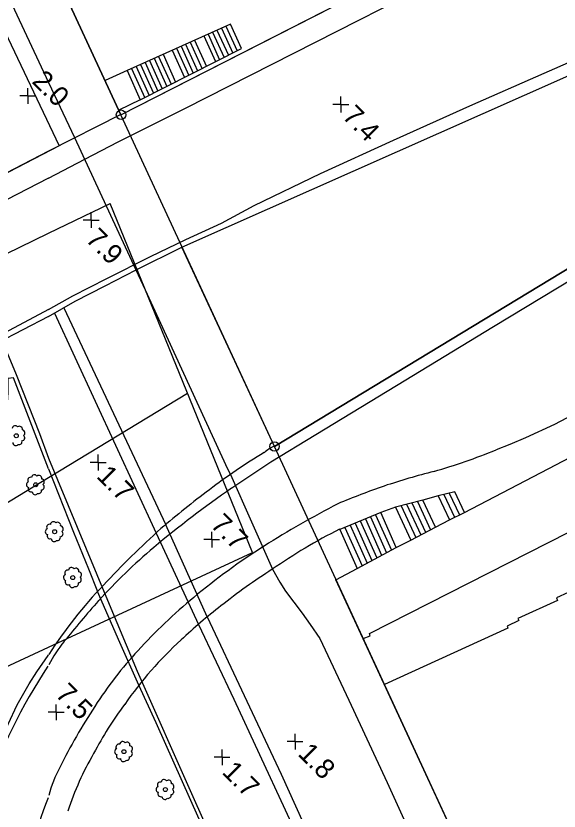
# Model space of a CAD drawing. Extents: x 1596643 to 1597288, y 13057194 to 13057957.
# Drawn here: x 1596964.2 to 1597032.9, y 13057515.8 to 13057616.2 of the extents above; entities that cross this region are included whole.
import ezdxf

# ---------------------------------------------------------------- set-up
doc = ezdxf.new("R2010")
doc.units = 0
for name, color, linetype in [('BAS bro ej def L', 7, 'Continuous'), ('BAS byggnad anläggning L', 7, 'Continuous'), ('BAS fastighetsgräns samfällighet L', 7, 'Continuous'), ('BAS gränspunkt P', 7, 'Continuous'), ('BAS Level 16', 7, 'Continuous'), ('BAS Level 19', 7, 'Continuous'), ('BAS Level 37', 7, 'Continuous'), ('BAS lövträd P', 7, 'Continuous'), ('BAS markytetext T', 7, 'Continuous'), ('BAS trappa L', 7, 'Continuous'), ('BAS vägbanekant L', 7, 'Continuous'), ('BAS vägbanekant skymd L', 7, 'Continuous')]:
    doc.layers.add(name, color=color, linetype=linetype)

msp = doc.modelspace()

# ---------------------------------------------------------------- linework, layer by layer
at = {"layer": 'BAS bro ej def L'}
for points in [[(1596977.5, 13057603.75), (1596968.37, 13057599.11)], [(1596968.37, 13057599.11), (1596945.61, 13057587.34)], [(1596968.37, 13057578.26), (1596971.71, 13057580.17), (1596975.51, 13057582.13), (1596979.42, 13057584.14), (1596985.19, 13057586.99)], [(1596968.37, 13057578.26), (1596961.83, 13057574.87), (1596953.74, 13057570.55), (1596946.34, 13057566.85), (1596942.26, 13057564.19), (1596937.94, 13057561.2), (1596935.83, 13057559.68), (1596934.45, 13057558.59), (1596933, 13057557.36), (1596931.11, 13057555.5), (1596929.21, 13057553.09), (1596927.13, 13057550.32), (1596925.83, 13057548.44), (1596924.41, 13057546.08), (1596923.09, 13057543.75), (1596922.68, 13057542.79)], [(1596968.37, 13057559.03), (1596963.92, 13057570.5), (1596963.21, 13057570.42), (1596963.2, 13057568.81), (1596963.17, 13057567.8), (1596963.02, 13057566.91), (1596962.87, 13057566.1), (1596962.52, 13057564.51), (1596962.24, 13057563.63), (1596961.83, 13057562.46), (1596961.39, 13057561.38), (1596961.07, 13057560.47), (1596960.36, 13057559.01)], [(1596968.37, 13057559.03), (1596971.52, 13057551.03), (1596973.41, 13057546.38), (1596974.54, 13057543.54)], [(1596979.78, 13057531.7), (1596977.35, 13057537.08), (1596974.54, 13057543.54)], [(1596962.07, 13057524.36), (1596964.38, 13057529.23), (1596965.91, 13057531.86), (1596966.88, 13057533.38), (1596968.29, 13057535.47), (1596968.37, 13057535.59)], [(1596995.41, 13057497.02), (1596988.46, 13057512.45), (1596981.95, 13057526.95), (1596979.78, 13057531.7)]]:
    msp.add_lwpolyline(points, dxfattribs=at)
for centre, radius, start, end in [((1596999.18, 13057556.93), 5.46, 114.9282, 131.0153), ((1597029.85, 13057503.15), 67.28, 120.6001, 127.7266), ((1597053.55, 13057468.94), 108.86, 126.5796, 130.7023), ((1597063.17, 13057461.96), 120.46, 132.0042, 136.8468), ((1597037.61, 13057487.26), 71.9, 116.8673, 124.7464), ((1597040.07, 13057478.64), 80.44, 122.6844, 128.3698), ((1597020.72, 13057501.31), 62.57, 136.5458, 146.778), ((1597027.18, 13057493.22), 61.01, 127.3785, 133.5895), ((1597017.61, 13057501.73), 48.26, 132.3279, 145.1907), ((1597016.35, 13057500.68), 47.86, 143.2958, 152.092), ((1597006.98, 13057503.99), 38.06, 149.8884, 161.9045)]:
    msp.add_arc(centre, radius, start, end, dxfattribs=at)
at = {"layer": 'BAS byggnad anläggning L'}
for points in [[(1596968.37, 13057623.46), (1596977.51, 13057603.71), (1597028.78, 13057629.87)], [(1596996.9, 13057561.83), (1596985.19, 13057586.99), (1597077.39, 13057627.92), (1597084.1, 13057614.57), (1597047.16, 13057592.27), (1596996.9, 13057561.83)], [(1597020.93, 13057553.52), (1597056.53, 13057572.05)], [(1597017.26, 13057551.65), (1597019.03, 13057552.58)], [(1597012.3, 13057549.1), (1597014.13, 13057550.02)], [(1597004.68, 13057545.02), (1597007.37, 13057546.44)], [(1597026.09, 13057498.76), (1597004.68, 13057545.02)]]:
    msp.add_lwpolyline(points, dxfattribs=at)
at = {"layer": 'BAS fastighetsgräns samfällighet L'}
for points in [[(1596920.39, 13057703.46), (1596969.69, 13057599.79)], [(1596969.69, 13057599.79), (1596957.92, 13057593.7)], [(1596968.37, 13057588.76), (1596976.14, 13057592.53)], [(1596968.37, 13057536.52), (1596994.11, 13057548.45), (1596976.14, 13057592.53)], [(1596927.35, 13057566.95), (1596943.41, 13057576.18), (1596950.44, 13057580.05), (1596968.37, 13057588.76)], [(1596968.37, 13057557.92), (1596985.92, 13057568.57)], [(1596934.7, 13057537.49), (1596968.37, 13057557.92)], [(1596942.22, 13057524.4), (1596968.37, 13057536.52)]]:
    msp.add_lwpolyline(points, dxfattribs=at)
at = {"layer": 'BAS gränspunkt P'}
for centre, radius in [((1596977.52, 13057603.72), 0.6), ((1596977.52, 13057603.72), 0.6), ((1596977.51, 13057603.71), 0.001), ((1596977.51, 13057603.71), 0.001), ((1596996.91, 13057561.84), 0.6), ((1596996.91, 13057561.84), 0.6), ((1596996.9, 13057561.83), 0.001), ((1596996.9, 13057561.83), 0.001)]:
    msp.add_circle(centre, radius, dxfattribs=at)
at = {"layer": 'BAS Level 16'}
for p, q in [((1596965.73, 13057606.09), (1596965.73, 13057607.09)), ((1596965.73, 13057606.09), (1596965.73, 13057607.09)), ((1596965.73, 13057606.09), (1596964.73, 13057606.09)), ((1596965.73, 13057606.09), (1596964.73, 13057606.09)), ((1596965.73, 13057606.09), (1596966.73, 13057606.09)), ((1596965.73, 13057606.09), (1596965.73, 13057605.09)), ((1596965.73, 13057606.09), (1596966.73, 13057606.09)), ((1596965.73, 13057606.09), (1596965.73, 13057605.09)), ((1597005.29, 13057605.01), (1597005.29, 13057606.01)), ((1597005.29, 13057605.01), (1597005.29, 13057606.01)), ((1597005.29, 13057605.01), (1597004.29, 13057605.01)), ((1597005.29, 13057605.01), (1597004.29, 13057605.01)), ((1597005.29, 13057605.01), (1597006.29, 13057605.01)), ((1597005.29, 13057605.01), (1597005.29, 13057604.01)), ((1597005.29, 13057605.01), (1597006.29, 13057605.01)), ((1597005.29, 13057605.01), (1597005.29, 13057604.01)), ((1596973.74, 13057590.42), (1596973.74, 13057591.42)), ((1596973.74, 13057590.42), (1596973.74, 13057591.42)), ((1596973.74, 13057590.42), (1596972.74, 13057590.42)), ((1596973.74, 13057590.42), (1596972.74, 13057590.42)), ((1596973.74, 13057590.42), (1596974.74, 13057590.42)), ((1596973.74, 13057590.42), (1596973.74, 13057589.42)), ((1596973.74, 13057590.42), (1596974.74, 13057590.42)), ((1596973.74, 13057590.42), (1596973.74, 13057589.42)), ((1596974.63, 13057559.81), (1596974.63, 13057560.81)), ((1596974.63, 13057559.81), (1596974.63, 13057560.81)), ((1596974.63, 13057559.81), (1596973.63, 13057559.81)), ((1596974.63, 13057559.81), (1596973.63, 13057559.81)), ((1596974.63, 13057559.81), (1596975.63, 13057559.81)), ((1596974.63, 13057559.81), (1596974.63, 13057558.81)), ((1596974.63, 13057559.81), (1596975.63, 13057559.81)), ((1596974.63, 13057559.81), (1596974.63, 13057558.81)), ((1596988.97, 13057550.08), (1596988.97, 13057551.08)), ((1596988.97, 13057550.08), (1596988.97, 13057551.08)), ((1596988.97, 13057550.08), (1596987.97, 13057550.08)), ((1596988.97, 13057550.08), (1596987.97, 13057550.08)), ((1596988.97, 13057550.08), (1596989.97, 13057550.08)), ((1596988.97, 13057550.08), (1596988.97, 13057549.08)), ((1596988.97, 13057550.08), (1596989.97, 13057550.08)), ((1596988.97, 13057550.08), (1596988.97, 13057549.08)), ((1596969.33, 13057528.28), (1596969.33, 13057529.28)), ((1596969.33, 13057528.28), (1596969.33, 13057529.28)), ((1596969.33, 13057528.28), (1596968.33, 13057528.28)), ((1596969.33, 13057528.28), (1596968.33, 13057528.28)), ((1596969.33, 13057528.28), (1596970.33, 13057528.28)), ((1596969.33, 13057528.28), (1596969.33, 13057527.28)), ((1596969.33, 13057528.28), (1596970.33, 13057528.28)), ((1596969.33, 13057528.28), (1596969.33, 13057527.28)), ((1596999.51, 13057524.58), (1596999.51, 13057525.58)), ((1596999.51, 13057524.58), (1596999.51, 13057525.58)), ((1596999.51, 13057524.58), (1596998.51, 13057524.58)), ((1596999.51, 13057524.58), (1596998.51, 13057524.58)), ((1596999.51, 13057524.58), (1597000.51, 13057524.58)), ((1596999.51, 13057524.58), (1596999.51, 13057523.58)), ((1596999.51, 13057524.58), (1597000.51, 13057524.58)), ((1596999.51, 13057524.58), (1596999.51, 13057523.58)), ((1596990.28, 13057522.6), (1596990.28, 13057523.6)), ((1596990.28, 13057522.6), (1596990.28, 13057523.6)), ((1596990.28, 13057522.6), (1596989.28, 13057522.6)), ((1596990.28, 13057522.6), (1596989.28, 13057522.6)), ((1596990.28, 13057522.6), (1596991.28, 13057522.6)), ((1596990.28, 13057522.6), (1596990.28, 13057521.6)), ((1596990.28, 13057522.6), (1596991.28, 13057522.6)), ((1596990.28, 13057522.6), (1596990.28, 13057521.6))]:
    msp.add_line(p, q, dxfattribs=at)
at = {"layer": 'BAS Level 19'}
for points in [[(1597017.6, 13057555.62), (1597015.66, 13057555.08)], [(1597012.2, 13057554.18), (1597010.33, 13057553.49)]]:
    msp.add_lwpolyline(points, dxfattribs=at)
at = {"layer": 'BAS Level 37'}
for points in [[(1596977.51, 13057603.71), (1596968.37, 13057623.46)], [(1596977.51, 13057603.71), (1597013.03, 13057621.86)], [(1596996.9, 13057561.83), (1596977.51, 13057603.71)], [(1596996.9, 13057561.83), (1597047.16, 13057592.27)], [(1597026.09, 13057498.76), (1596996.9, 13057561.83)]]:
    msp.add_lwpolyline(points, dxfattribs=at)
at = {"layer": 'BAS lövträd P'}
for p, q in [((1596964.28, 13057563.19), (1596964.28, 13057563.19)), ((1596964.28, 13057563.19), (1596964.28, 13057563.19)), ((1596966.73, 13057557), (1596966.73, 13057557)), ((1596966.73, 13057557), (1596966.73, 13057557)), ((1596969.13, 13057551.08), (1596969.13, 13057551.08)), ((1596969.13, 13057551.08), (1596969.13, 13057551.08)), ((1596971.42, 13057545.28), (1596971.42, 13057545.28)), ((1596971.42, 13057545.28), (1596971.42, 13057545.28)), ((1596977.88, 13057523.31), (1596977.88, 13057523.31)), ((1596977.88, 13057523.31), (1596977.88, 13057523.31)), ((1596983.12, 13057518.53), (1596983.12, 13057518.53)), ((1596983.12, 13057518.53), (1596983.12, 13057518.53))]:
    msp.add_line(p, q, dxfattribs=at)
for centre in [(1596964.28, 13057563.19), (1596964.28, 13057563.19), (1596966.73, 13057557), (1596966.73, 13057557), (1596969.13, 13057551.08), (1596969.13, 13057551.08), (1596971.42, 13057545.28), (1596971.42, 13057545.28), (1596977.88, 13057523.31), (1596977.88, 13057523.31), (1596983.12, 13057518.53), (1596983.12, 13057518.53)]:
    msp.add_circle(centre, 0.25, dxfattribs=at)
for centre, start, end in [((1596964.13, 13057564.09), 33.6442, 175.122), ((1596964.13, 13057564.09), 33.6442, 175.122), ((1596964.68, 13057564.01), 347.9148, 129.3927), ((1596964.68, 13057564.01), 347.9148, 129.3927), ((1596965, 13057563.56), 301.358, 82.8359), ((1596965, 13057563.56), 301.358, 82.8359), ((1596964.98, 13057562.93), 273.337, 54.8149), ((1596964.98, 13057562.93), 273.337, 54.8149), ((1596964.22, 13057562.32), 179.8192, 321.2971), ((1596964.22, 13057562.32), 179.8192, 321.2971), ((1596964.64, 13057562.46), 253.1363, 15.428), ((1596964.64, 13057562.46), 253.1363, 15.428), ((1596966.1, 13057557.57), 73.076, 214.5539), ((1596966.1, 13057557.57), 73.076, 214.5539), ((1596966.58, 13057557.89), 33.6442, 175.122), ((1596966.58, 13057557.89), 33.6442, 175.122), ((1596967.13, 13057557.81), 347.9148, 129.3927), ((1596967.13, 13057557.81), 347.9148, 129.3927), ((1596967.45, 13057557.36), 301.358, 82.8359), ((1596967.45, 13057557.36), 301.358, 82.8359), ((1596965.93, 13057557.01), 112.5079, 253.9858), ((1596965.93, 13057557.01), 112.5079, 253.9858), ((1596966.16, 13057556.47), 151.3828, 292.8606), ((1596966.16, 13057556.47), 151.3828, 292.8606), ((1596967.43, 13057556.73), 273.337, 54.8149), ((1596967.43, 13057556.73), 273.337, 54.8149), ((1596966.68, 13057556.12), 179.8192, 321.2971), ((1596966.68, 13057556.12), 179.8192, 321.2971), ((1596967.09, 13057556.26), 253.1363, 15.428), ((1596967.09, 13057556.26), 253.1363, 15.428), ((1596968.49, 13057551.65), 73.076, 214.5539), ((1596968.49, 13057551.65), 73.076, 214.5539), ((1596968.97, 13057551.97), 33.6442, 175.122), ((1596968.97, 13057551.97), 33.6442, 175.122), ((1596969.52, 13057551.89), 347.9148, 129.3927), ((1596969.52, 13057551.89), 347.9148, 129.3927), ((1596969.84, 13057551.44), 301.358, 82.8359), ((1596969.84, 13057551.44), 301.358, 82.8359), ((1596968.32, 13057551.09), 112.5079, 253.9858), ((1596968.32, 13057551.09), 112.5079, 253.9858), ((1596968.55, 13057550.55), 151.3828, 292.8606), ((1596968.55, 13057550.55), 151.3828, 292.8606), ((1596969.82, 13057550.81), 273.337, 54.8149), ((1596969.82, 13057550.81), 273.337, 54.8149), ((1596969.07, 13057550.2), 179.8192, 321.2971), ((1596969.07, 13057550.2), 179.8192, 321.2971), ((1596969.48, 13057550.34), 253.1363, 15.428), ((1596969.48, 13057550.34), 253.1363, 15.428), ((1596971.27, 13057546.18), 33.6442, 175.122), ((1596971.27, 13057546.18), 33.6442, 175.122), ((1596970.62, 13057545.29), 112.5079, 253.9858), ((1596970.62, 13057545.29), 112.5079, 253.9858), ((1596970.78, 13057545.85), 73.076, 214.5539), ((1596970.78, 13057545.85), 73.076, 214.5539), ((1596971.82, 13057546.09), 347.9148, 129.3927), ((1596971.82, 13057546.09), 347.9148, 129.3927), ((1596972.14, 13057545.64), 301.358, 82.8359), ((1596972.14, 13057545.64), 301.358, 82.8359), ((1596970.84, 13057544.75), 151.3828, 292.8606), ((1596970.84, 13057544.75), 151.3828, 292.8606), ((1596971.78, 13057544.54), 253.1363, 15.428), ((1596971.78, 13057544.54), 253.1363, 15.428), ((1596972.12, 13057545.02), 273.337, 54.8149), ((1596972.12, 13057545.02), 273.337, 54.8149), ((1596971.36, 13057544.4), 179.8192, 321.2971), ((1596971.36, 13057544.4), 179.8192, 321.2971), ((1596977.72, 13057524.21), 33.6442, 175.122), ((1596977.72, 13057524.21), 33.6442, 175.122), ((1596978.27, 13057524.13), 347.9148, 129.3927), ((1596978.27, 13057524.13), 347.9148, 129.3927), ((1596977.08, 13057523.32), 112.5079, 253.9858), ((1596977.08, 13057523.32), 112.5079, 253.9858), ((1596977.24, 13057523.88), 73.076, 214.5539), ((1596977.24, 13057523.88), 73.076, 214.5539), ((1596978.59, 13057523.68), 301.358, 82.8359), ((1596978.59, 13057523.68), 301.358, 82.8359), ((1596977.3, 13057522.78), 151.3828, 292.8606), ((1596977.3, 13057522.78), 151.3828, 292.8606), ((1596978.23, 13057522.58), 253.1363, 15.428), ((1596978.23, 13057522.58), 253.1363, 15.428), ((1596978.57, 13057523.05), 273.337, 54.8149), ((1596978.57, 13057523.05), 273.337, 54.8149), ((1596977.82, 13057522.44), 179.8192, 321.2971), ((1596977.82, 13057522.44), 179.8192, 321.2971), ((1596982.48, 13057519.1), 73.076, 214.5539), ((1596982.48, 13057519.1), 73.076, 214.5539), ((1596982.96, 13057519.42), 33.6442, 175.122), ((1596982.96, 13057519.42), 33.6442, 175.122), ((1596983.51, 13057519.34), 347.9148, 129.3927), ((1596983.51, 13057519.34), 347.9148, 129.3927), ((1596982.31, 13057518.54), 112.5079, 253.9858), ((1596982.31, 13057518.54), 112.5079, 253.9858), ((1596983.81, 13057518.26), 273.337, 54.8149), ((1596983.81, 13057518.26), 273.337, 54.8149), ((1596983.83, 13057518.89), 301.358, 82.8359), ((1596983.83, 13057518.89), 301.358, 82.8359), ((1596982.54, 13057518), 151.3828, 292.8606), ((1596982.54, 13057518), 151.3828, 292.8606), ((1596983.06, 13057517.65), 179.8192, 321.2971), ((1596983.06, 13057517.65), 179.8192, 321.2971), ((1596983.47, 13057517.79), 253.1363, 15.428), ((1596983.47, 13057517.79), 253.1363, 15.428)]:
    msp.add_arc(centre, 0.375, start, end, dxfattribs=at)
at = {"layer": 'BAS trappa L'}
for points in [[(1596991.35, 13057615.17), (1596978.29, 13057609.31)], [(1596990.78, 13057614.92), (1596992.21, 13057611.79)], [(1596992.76, 13057612.08), (1596991.35, 13057615.17)], [(1596988.51, 13057613.9), (1596989.98, 13057610.66)], [(1596989.08, 13057614.15), (1596990.54, 13057610.95)], [(1596989.64, 13057614.41), (1596991.09, 13057611.23)], [(1596990.21, 13057614.66), (1596991.65, 13057611.51)], [(1596986.24, 13057612.88), (1596987.75, 13057609.53)], [(1596986.8, 13057613.13), (1596988.31, 13057609.82)], [(1596987.98, 13057613.66), (1596989.45, 13057610.43)], [(1596979.95, 13057605.58), (1596992.76, 13057612.08)], [(1596983.96, 13057611.86), (1596985.52, 13057608.4)], [(1596984.53, 13057612.11), (1596986.08, 13057608.69)], [(1596985.1, 13057612.37), (1596986.63, 13057608.97)], [(1596985.67, 13057612.62), (1596987.19, 13057609.25)], [(1596981.69, 13057610.84), (1596983.29, 13057607.27)], [(1596982.26, 13057611.09), (1596983.85, 13057607.56)], [(1596982.83, 13057611.35), (1596984.41, 13057607.84)], [(1596979.42, 13057609.82), (1596981.06, 13057606.14)], [(1596979.99, 13057610.07), (1596981.62, 13057606.43)], [(1596980.56, 13057610.33), (1596982.18, 13057606.71)], [(1596981.13, 13057610.58), (1596982.73, 13057606.99)], [(1596978.29, 13057609.31), (1596975.5, 13057608.06)], [(1596978.29, 13057609.31), (1596979.95, 13057605.58)], [(1596978.85, 13057609.56), (1596980.51, 13057605.86)], [(1596979.95, 13057605.58), (1596977.24, 13057604.29)], [(1597019.7, 13057556.13), (1597017.6, 13057555.62)], [(1597017.6, 13057555.62), (1597019.03, 13057552.58)], [(1597018.3, 13057555.79), (1597019.66, 13057552.9)], [(1597019, 13057555.96), (1597020.3, 13057553.21)], [(1597020.93, 13057553.52), (1597019.7, 13057556.13)], [(1597015.66, 13057555.08), (1597012.2, 13057554.18)], [(1597014.28, 13057554.72), (1597016.01, 13057551)], [(1597014.97, 13057554.9), (1597016.64, 13057551.32)], [(1597017.26, 13057551.65), (1597015.66, 13057555.08)], [(1597012.2, 13057554.18), (1597014.13, 13057550.02)], [(1597012.9, 13057554.36), (1597014.76, 13057550.34)], [(1597013.59, 13057554.54), (1597015.38, 13057550.67)], [(1597010.33, 13057553.49), (1597005.16, 13057551.36)], [(1597008.39, 13057552.69), (1597010.45, 13057548.1)], [(1597009.04, 13057552.96), (1597011.07, 13057548.43)], [(1597009.69, 13057553.22), (1597011.68, 13057548.76)], [(1597012.3, 13057549.1), (1597010.33, 13057553.49)], [(1597019.03, 13057552.58), (1597020.93, 13057553.52)], [(1597005.81, 13057551.63), (1597007.99, 13057546.77)], [(1597006.46, 13057551.89), (1597008.6, 13057547.1)], [(1597007.1, 13057552.16), (1597009.22, 13057547.44)], [(1597007.75, 13057552.43), (1597009.83, 13057547.77)], [(1597014.13, 13057550.02), (1597017.26, 13057551.65)], [(1597005.16, 13057551.36), (1597007.37, 13057546.44)], [(1597007.37, 13057546.44), (1597012.3, 13057549.1)]]:
    msp.add_lwpolyline(points, dxfattribs=at)
at = {"layer": 'BAS vägbanekant L'}
for points in [[(1596946.15, 13057659.15), (1596946.17, 13057659.07), (1596946.92, 13057655.49), (1596947.51, 13057652.92), (1596947.69, 13057652.36), (1596948.14, 13057651.39), (1596951.43, 13057644.24), (1596957.49, 13057631.32), (1596963.14, 13057618.98), (1596968.37, 13057607.8)], [(1596968.37, 13057595.73), (1596972.95, 13057598.13), (1596977.16, 13057600.28), (1596985.67, 13057604.56), (1597002.09, 13057612.9), (1597015.87, 13057619.92), (1597028.2, 13057626.27), (1597039.31, 13057631.84), (1597049.73, 13057637.17), (1597061.87, 13057643.37), (1597074.42, 13057649.69), (1597075.38, 13057650.29)], [(1596968.37, 13057579.11), (1596971.42, 13057580.85), (1596975.73, 13057583.06), (1596981.26, 13057585.82), (1596985.71, 13057587.98), (1596990.2, 13057590.03), (1596994.33, 13057592.27), (1597002.73, 13057596.3), (1597011.95, 13057600.51), (1597021.61, 13057604.85), (1597030.99, 13057608.98), (1597039.14, 13057612.55), (1597043.41, 13057614.5), (1597052.02, 13057618.35), (1597069.31, 13057625.96), (1597094.21, 13057637)], [(1597089.18, 13057616.01), (1597086.55, 13057614.49), (1597080.09, 13057610.48), (1597070.6, 13057604.79), (1597059.78, 13057598.22), (1597049.35, 13057591.94), (1597038.73, 13057585.48), (1597024.58, 13057576.95), (1597012.32, 13057569.51), (1597002.12, 13057563.32), (1596996.45, 13057559.86), (1596991.5, 13057556.56)], [(1596968.37, 13057607.8), (1596971.62, 13057600.83)], [(1596968.37, 13057595.73), (1596951.07, 13057586.84), (1596934.69, 13057578.38), (1596919.64, 13057570.7), (1596906.07, 13057563.73), (1596892.75, 13057556.93), (1596882.72, 13057551.85), (1596869.69, 13057545.17), (1596859.15, 13057539.72), (1596850.2, 13057535.12), (1596841.05, 13057530.42), (1596829.94, 13057524.84), (1596820.55, 13057520.23), (1596817.46, 13057518.69), (1596815.33, 13057517.84), (1596812.85, 13057516.8), (1596811.58, 13057516.31)], [(1597084.79, 13057591.89), (1597077.3, 13057587.98), (1597064.49, 13057581.37), (1597052.86, 13057575.34), (1597038.61, 13057567.93), (1597032.31, 13057564.62), (1597028.62, 13057562.91), (1597026.65, 13057562.1), (1597024.91, 13057561.4)], [(1596979.4, 13057584.13), (1596980.56, 13057581.63), (1596990.98, 13057559.02), (1596991.34, 13057558.31)], [(1596968.37, 13057579.11), (1596961.43, 13057575.47), (1596955.01, 13057572.03), (1596951.14, 13057569.92), (1596946.71, 13057567.39), (1596944.08, 13057565.86), (1596941.67, 13057564.34), (1596939.51, 13057562.89), (1596937, 13057561.14), (1596935.15, 13057559.73), (1596933.98, 13057558.63), (1596932.32, 13057557.24), (1596930.65, 13057555.61), (1596929.93, 13057554.85), (1596928.61, 13057553.29), (1596926.5, 13057550.68), (1596925.42, 13057549.13), (1596924.23, 13057547.22), (1596923.25, 13057545.53), (1596922.7, 13057544.24), (1596922.08, 13057542.99), (1596921.58, 13057541.99), (1596921.06, 13057540.94)], [(1596969.11, 13057578.68), (1596981.94, 13057550.9)], [(1596970.27, 13057579.34), (1596983.19, 13057551.93)], [(1596963.13, 13057573.65), (1596964.27, 13057570.91), (1596967.2, 13057563.46), (1596968.37, 13057560.37)], [(1596968.37, 13057560.37), (1596975.6, 13057542.92), (1596979.57, 13057533.49), (1596986.57, 13057517.64), (1596993.2, 13057502.84), (1596995.61, 13057497.03), (1596996.76, 13057494.11)], [(1596996.64, 13057546.34), (1596997.57, 13057544.7), (1596998.28, 13057543.59), (1597000.41, 13057540.8), (1597001.42, 13057539.36), (1597002.65, 13057537.61), (1597006.3, 13057529.82), (1597011.14, 13057519.4), (1597015.54, 13057509.8), (1597018.83, 13057502.61), (1597019.26, 13057501.7), (1597019.74, 13057500.99), (1597020.19, 13057500.3), (1597020.89, 13057499.42), (1597021.13, 13057499.06)], [(1596988.41, 13057540.33), (1596997.76, 13057520.45), (1597002.4, 13057510.24), (1597005.74, 13057502.91), (1597006.73, 13057500.82), (1597007.41, 13057499.5), (1597008.1, 13057498.34)], [(1596987.29, 13057539.38), (1596991.79, 13057529.93), (1596998.24, 13057515.95), (1597002.4, 13057507), (1597005.42, 13057500.56), (1597006.66, 13057498.09)]]:
    msp.add_lwpolyline(points, dxfattribs=at)
for centre, radius, start, end in [((1596994.37, 13057636.96), 81.49, 286.1676, 292.0044), ((1597042.78, 13057458.92), 103.03, 104.453, 108.1064), ((1597044.59, 13057459.95), 102.63, 109.2441, 112.7481), ((1597063.12, 13057452.05), 126.7, 124.424, 130.009), ((1597062.71, 13057442.98), 125.7, 117.3786, 122.2768), ((1597028.31, 13057493.61), 72.48, 130.0584, 137.7237), ((1597043.57, 13057474.24), 89.06, 122.6087, 129.6833), ((1597027.56, 13057492.82), 64.53, 129.2713, 137.9286), ((1597130.38, 13057406.29), 206.79, 138.847, 140.722), ((1596986.24, 13057524.6), 20.31, 141.6226, 151.5753), ((1597015.11, 13057502.99), 48.48, 136.9968, 147.511), ((1597028.79, 13057494.22), 72.47, 146.6005, 160.8645), ((1597034.44, 13057489.26), 72.17, 146.5599, 153.6231), ((1596984, 13057513.62), 16.17, 151.5533, 165.1076), ((1597024.75, 13057495.8), 60.48, 158.9894, 185.6739)]:
    msp.add_arc(centre, radius, start, end, dxfattribs=at)
at = {"layer": 'BAS vägbanekant skymd L'}
for points in [[(1596971.62, 13057600.83), (1596979.4, 13057584.13)], [(1596991.34, 13057558.31), (1596996.64, 13057546.34)], [(1597008.12, 13057537.59), (1597009.01, 13057537.95), (1597008.91, 13057538.23), (1597046.62, 13057557.39)], [(1597059.53, 13057557.46), (1597060.02, 13057556.49), (1597054.03, 13057553.71), (1597054.17, 13057553.35), (1597048.84, 13057550.86), (1597048.92, 13057550.59), (1597038.31, 13057545.75), (1597038.45, 13057545.41), (1597032.55, 13057542.74), (1597032.69, 13057542.4), (1597027.67, 13057540.13), (1597027.78, 13057539.88), (1597026.3, 13057539.15), (1597026.38, 13057538.9), (1597010.81, 13057531.77)], [(1596988.41, 13057540.33), (1596983.19, 13057551.93)], [(1596981.94, 13057550.9), (1596987.29, 13057539.38)]]:
    msp.add_lwpolyline(points, dxfattribs=at)

# ---------------------------------------------------------------- texts
at = {"layer": 'BAS markytetext T'}
for s, p in [('2.0', (1596966.15, 13057607.82)), ('7.4', (1597005.36, 13057603.4)), ('7.9', (1596972.93, 13057587.88)), ('1.7', (1596974.3, 13057557.96)), ('7.7', (1596988.71, 13057551.83)), ('7.5', (1596969.1, 13057530.43)), ('1.8', (1596999.76, 13057522.92)), ('1.7', (1596990.17, 13057520.62))]:
    msp.add_text(s, height=2.5, rotation=315, dxfattribs=at).set_placement(p)

doc.saveas('drawing.dxf')
